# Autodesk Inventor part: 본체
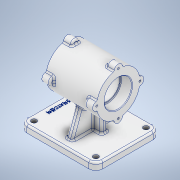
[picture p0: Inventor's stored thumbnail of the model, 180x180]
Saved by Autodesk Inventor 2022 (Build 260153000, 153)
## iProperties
Created: 2023-05
Part Number: 본체
Material: 알루미늄 6061
Document SubType Name: Modeling
Designer: Admin
Mass: 1215.37 g
Surface Area: 797.035 cm^2
Volume: 450.137 cm^3
Density: 2.7 g/cm^3
Appearance: 알루미늄 - 평지
Author: Admin
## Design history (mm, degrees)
sketch "스케치1"
  geometry: L1 (-60.9, 0)-(60.9, 0) reference; L2 (0, -7.4)-(0, 44.4) reference; L3 (-43.5, 0)-(43.5, 0); L4 (43.5, 0)-(43.5, 37); L5 (43.5, 37)-(-43.5, 37); L6 (-43.5, 37)-(-43.5, 0); 2 further points
  constraints: 8 end point, 2 parallel, 1 horizontal, 1 perpendicular, 1 point on line, 1 other
  dimensions: "d0" = 74 diameter of L5 L1; "d1" = 87 distance of L4.end L5.end
revolve "회전1" sketch "스케치1" stored, may be unused: angle "d2" = 90 deg
sketch "스케치2"
  geometry: C1 r 23.5 at (0, 0); 1 further point
  constraints: 1 centre point, 1 coincident
  dimensions: "d3" = 47 diameter of C1
extrude "돌출1" cut sketch "스케치2" distance "d4" = 19; taper "d5" = 0 deg
sketch "스케치3"
  geometry: C1 r 21 at (0, 0); 1 further point
  constraints: 1 centre point, 1 coincident
  dimensions: "d6" = 42 diameter of C1
extrude "돌출2" cut sketch "스케치3" distance "d7" = 49; taper "d8" = 0 deg
sketch "스케치4"
  geometry: C1 r 23.5 at (0, 0); 1 further point
  constraints: 1 centre point, 1 coincident
  dimensions: "d9" = 47 diameter of C1
extrude "돌출3" cut sketch "스케치4" distance "d10" = 19; taper "d11" = 0 deg
node "작업 평면1"
sketch "스케치8"
  geometry: L1 (0, -105.8)-(0, 60.8) reference; L2 (77, 0)-(-77, 0) reference; C1 r 37 at (0, 0) reference; C2 r 7 at (0, 37); 4 further points
  constraints: 1 centre point, 1 point on line, 2 other
  dimensions: "d32" = 14 diameter of C2
extrude "돌출7" join sketch "스케치8" distance "d33" = 14; taper "d34" = 0 deg
sketch "스케치12"
  geometry: A1 r 7 centre (0, 0) between (6.969, -0.662) and (-6.969, -0.662) reference; A2 r 7 centre (37, -37) between (36.338, -43.969) and (36.338, -30.031) reference; A3 r 7 centre (0, -74) between (-6.969, -73.338) and (6.969, -73.338) reference; A4 r 7 centre (-37, -37) between (-36.338, -30.031) and (-36.338, -43.969) reference; A5 r 7 centre (-37, -37) between (-36.338, -30.031) and (-36.338, -43.969) reference; 5 further points
  constraints: 4 coincident
hole "구멍2" sketch "스케치12" at (0, 0), (37, -37), (0, -74), (-37, -37) diameter "d46" = 3.242; stored, may be unused: countersink angle "d50" = 90 deg, drill point angle "d52" = 118 deg; dims "d47" = 8, "d48" = 4, "d49" = 2, "d51" = 10
node "작업 평면2"
sketch "스케치17"
  geometry: L1 (60.9, 0)-(-60.9, 0) reference; L2 (0, -61.6)-(0, 61.6) reference; L3 (-60, 55)-(70, 55); L4 (70, 55)-(70, -55); L5 (70, -55)-(-60, -55); L6 (-60, -55)-(-60, 55); L7 (-60, 55)-(70, -55); L8 (70, 55)-(-60, -55); L9 (43.5, -6.969)-(43.5, -36.338) reference; 2 further points
  constraints: 12 end point, 2 midpoint, 2 parallel, 1 horizontal, 1 perpendicular, 1 point on line
  dimensions: "d63" = 130 distance of L4.end L5.end; "d64" = 110 distance of L5.end L3.start; "d66" = 5 distance of point (0, 0) point (5, 0)
extrude "돌출9" join sketch "스케치17" distance "d67" = 12; taper "d68" = 0 deg
sketch "스케치18"
  geometry: L1 (-20, 5)-(20, 5); L2 (20, 5)-(20, -5); L3 (20, -5)-(-20, -5); L4 (-20, -5)-(-20, 5); L5 (-20, 5)-(20, -5); L6 (20, 5)-(-20, -5); 1 further point
  constraints: 12 end point, 2 midpoint, 2 parallel, 1 horizontal, 1 perpendicular
  dimensions: "d69" = 10 distance of L3.end L1.start; "d70" = 40 distance of L2.end L3.end
extrude "돌출10" join sketch "스케치18" stored distance "d71" = 12; taper "d72" = 0 deg
sketch "스케치19"
  geometry: L1 (-26.964, -25.336)-(-70, -41); L2 (-70, 55)-(-70, -55) reference; L3 (-26.964, 25.336)-(-70, 41); L4 (-82, -55)-(-70, -55) reference; L5 (-82, 55)-(-70, 55) reference; L6 (-70, -41)-(-70, 41); A1 r 37 centre (0, 0) between (-36.338, -6.969) and (-6.969, -36.338) reference; A2 r 37 centre (0, 0) between (-6.969, 36.338) and (-36.338, 6.969) reference; A3 r 37 centre (0, 0) between (-26.964, 25.336) and (-26.964, -25.336); 1 further point
  constraints: 6 end point, 4 point on circle, 2 point on line, 1 centre point, 1 coincident, 1 collinear
  dimensions: "d73" = 14 distance from line of L4 L1.end; "d74" = 14 distance from line of L5 L3.end; "d75" = 110 deg angle of L2 L1; "d76" = 110 deg angle of L2 L3
extrude "돌출11" join sketch "스케치19" stored distance "d77" = 10; taper "d78" = 0 deg
fillet "모깎기2" dims "d79" = 12
sketch "스케치20"
  geometry: A1 r 12 centre (48, 43) between (60, 43) and (48, 55) reference; A2 r 12 centre (48, -43) between (48, -55) and (60, -43) reference; A3 r 12 centre (-58, -43) between (-70, -43) and (-58, -55) reference; A4 r 12 centre (-58, 43) between (-58, 55) and (-70, 43) reference; 5 further points
  constraints: 4 coincident
hole "구멍3" sketch "스케치20" at (-58, 43), (48, 43), (48, -43), (-58, -43) diameter "d80" = 9; stored, may be unused: countersink angle "d84" = 90 deg, drill point angle "d86" = 118 deg; dims "d81" = 8, "d82" = 4, "d83" = 2, "d85" = 10
sketch "스케치21"
  geometry: L1 (-96, 0)-(86, 0) reference; 2 further points
  constraints: 1 point on line, 1 other
  dimensions: "d87" = 58 distance of point (0, 0) point (-58, 0)
feature "엠보싱2" sketch "스케치21" dims "d88" = 0.5, "d89" = 0
chamfer "모따기1" distance "d90" = 1; stored, may be unused: second distance "d91" = 2, angle "d92" = 45 deg
fillet "모깎기3" dims "d93" = 1
fillet "모깎기4" dims "d94" = 3
fillet "모깎기5" dims "d95" = 3
fillet "모깎기6" dims "d96" = 3
fillet "모깎기7" dims "d97" = 3
node "솔리드1"
pattern_circular "원형 패턴1" dims angle "d36" = 360 deg
mirror "미러1"
mirror "미러2"
feature "A9D066F2-1C7D-4E18-AEED-F7BC21143FA4" dims "d80" = 9, "d81" = 8, "d82" = 4, "d83" = 2, "d84" = 90 deg, "d85" = 10, "d86" = 118 deg
other parameters: "d12" = -82, "d62" = -82
